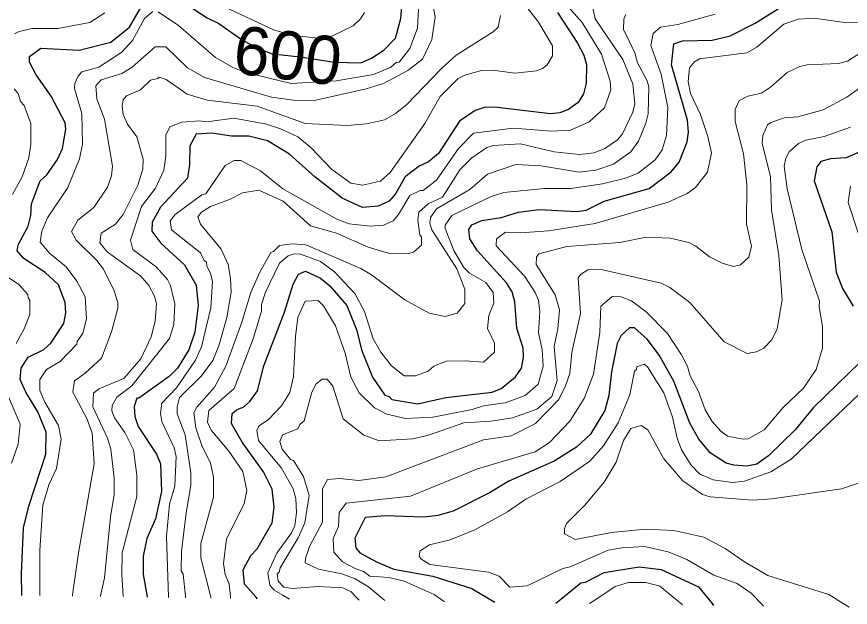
# Model space of a CAD drawing. Extents: x 673.3 to 698.5, y 6984.3 to 7012.3.
# Drawn here: x 678.213 to 679.596, y 6984.53 to 6985.511 of the extents above; entities that cross this region are included whole.
import ezdxf
from ezdxf.enums import TextEntityAlignment as Align

# ---------------------------------------------------------------- set-up
doc = ezdxf.new("R2010")
doc.units = 0
doc.header["$LTSCALE"] = 0.032
doc.layers.add('1', color=7, linetype='Continuous', lineweight=25)
doc.layers.add('2', color=7, linetype='Continuous', lineweight=13)
doc.layers.add('61', color=7, linetype='Continuous')

msp = doc.modelspace()

# ---------------------------------------------------------------- linework, layer by layer
at = {"layer": '1'}
for points in [[(678.2216, 6984.5503), (678.2208, 6984.5864), (678.2243, 6984.6624), (678.2328, 6984.6983), (678.2611, 6984.7846), (678.2617, 6984.8213), (678.2481, 6984.8546), (678.2282, 6984.8877), (678.2189, 6984.9087), (678.2201, 6984.9273), (678.2317, 6984.9453), (678.258, 6984.9585), (678.2697, 6984.9686), (678.2911, 6985.0015), (678.2943, 6985.0191), (678.2934, 6985.0361), (678.2821, 6985.0658), (678.2604, 6985.0859), (678.2248, 6985.1091), (678.2138, 6985.1221), (678.2152, 6985.1319), (678.2317, 6985.1631), (678.2365, 6985.1806), (678.2376, 6985.1998), (678.2518, 6985.2382), (678.2631, 6985.2482), (678.2807, 6985.2738), (678.2887, 6985.2917), (678.2943, 6985.3236), (678.2935, 6985.3345), (678.2703, 6985.3784), (678.2453, 6985.4138), (678.2342, 6985.4353), (678.2341, 6985.4442), (678.2531, 6985.4583), (678.3166, 6985.4552), (678.369, 6985.4685), (678.4003, 6985.493), (678.4288, 6985.5432)], [(678.494, 6985.5311), (678.5291, 6985.5084), (678.5483, 6985.4994), (678.5875, 6985.4717), (678.6144, 6985.4577), (678.6371, 6985.4491), (678.6835, 6985.4437), (678.7395, 6985.4348), (678.7837, 6985.434), (678.8014, 6985.4419), (678.822, 6985.4551), (678.8415, 6985.4747), (678.8504, 6985.5074), (678.8521, 6985.527)], [(678.6127, 6984.5446), (678.6097, 6984.548), (678.5908, 6984.5691), (678.5888, 6984.5925), (678.6012, 6984.6165), (678.6119, 6984.6275), (678.6367, 6984.6706), (678.6404, 6984.6966), (678.6371, 6984.7265), (678.6227, 6984.7553), (678.587, 6984.8046), (678.5691, 6984.8355), (678.5706, 6984.8518), (678.5777, 6984.8581), (678.5899, 6984.8631), (678.5996, 6984.8719), (678.6127, 6984.8899), (678.6229, 6984.9311), (678.6573, 6985.0204), (678.6716, 6985.0669), (678.6803, 6985.0835), (678.692, 6985.0884), (678.7169, 6985.0764), (678.7326, 6985.0639), (678.7609, 6985.0314), (678.7773, 6984.9897), (678.7851, 6984.9579), (678.8032, 6984.9122), (678.824, 6984.8825), (678.831, 6984.8801), (678.8352, 6984.8753), (678.8785, 6984.868), (678.9251, 6984.8787), (679.0017, 6984.8874), (679.0169, 6984.8935), (679.0404, 6984.913), (679.0508, 6984.9275), (679.0541, 6984.9458), (679.0533, 6984.9607), (679.0427, 6984.9936), (679.0395, 6985.0373), (679.0353, 6985.0539), (679.0258, 6985.0689), (678.9773, 6985.1222), (678.9646, 6985.1419), (678.963, 6985.1575), (678.968, 6985.1651), (678.9847, 6985.1723), (679.0167, 6985.1774), (679.0454, 6985.1862), (679.0799, 6985.1904), (679.1424, 6985.1872), (679.1581, 6985.1896), (679.1877, 6985.2042), (679.2623, 6985.2253), (679.299, 6985.2529), (679.3121, 6985.2691), (679.3254, 6985.3031), (679.3277, 6985.3188), (679.3262, 6985.3389), (679.2993, 6985.4304), (679.3033, 6985.4653), (679.3178, 6985.4705), (679.3671, 6985.4714), (679.3969, 6985.479), (679.4383, 6985.4997), (679.4904, 6985.5323)], [(679.1103, 6985.5174), (679.1436, 6985.4667), (679.1542, 6985.4464), (679.1584, 6985.4314), (679.1578, 6985.4002), (679.1535, 6985.3827), (679.1447, 6985.3682), (679.1288, 6985.3564), (679.1141, 6985.3508), (679.0988, 6985.3493), (679.0056, 6985.3606), (678.989, 6985.3598), (678.9737, 6985.3546), (678.9478, 6985.3373), (678.9126, 6985.2835), (678.8962, 6985.2695), (678.8809, 6985.2626), (678.8575, 6985.2446), (678.8415, 6985.2165), (678.831, 6985.2043), (678.8128, 6985.1961), (678.7868, 6985.1938), (678.7528, 6985.2091), (678.7078, 6985.2445), (678.6654, 6985.2826), (678.6293, 6985.3043), (678.5981, 6985.3125), (678.5691, 6985.3125), (678.5369, 6985.3174), (678.5109, 6985.3157), (678.5003, 6985.296), (678.4995, 6985.265), (678.4961, 6985.2425), (678.4516, 6985.1944), (678.4377, 6985.1697), (678.4369, 6985.1548), (678.4518, 6985.1347), (678.4913, 6985.0985), (678.5109, 6985.065)], [(679.6245, 6985.2916), (679.5896, 6985.2763), (679.5635, 6985.2745), (679.5474, 6985.27), (679.5404, 6985.2612), (679.5363, 6985.2379), (679.5654, 6985.1536), (679.5725, 6985.0866), (679.583, 6985.0595), (679.6009, 6985.0302)], [(678.5109, 6985.065), (678.5142, 6985.0311), (678.5086, 6984.9871), (678.4988, 6984.9578), (678.4798, 6984.9271), (678.4659, 6984.9134), (678.4154, 6984.8773), (678.4125, 6984.8774), (678.4077, 6984.8639), (678.4091, 6984.8471), (678.4142, 6984.8302), (678.4451, 6984.7846), (678.4515, 6984.7685), (678.4531, 6984.7226), (678.4433, 6984.6774), (678.4287, 6984.6448), (678.423, 6984.6151), (678.423, 6984.5848), (678.4288, 6984.5512), (678.4295, 6984.5473)], [(679.6127, 6984.9372), (679.5352, 6984.862), (679.5049, 6984.825), (679.4607, 6984.7818), (679.4409, 6984.7678), (679.4245, 6984.7646), (679.4027, 6984.7662), (679.3904, 6984.7699), (679.3639, 6984.7869), (679.3449, 6984.8092), (679.33, 6984.8359), (679.3032, 6984.9057), (679.2791, 6984.9488), (679.2595, 6984.9751), (679.2379, 6984.9941), (679.2296, 6984.9941), (679.2161, 6984.9817), (679.2092, 6984.9682), (679.1999, 6984.9213), (679.1957, 6984.8819), (679.1886, 6984.8568), (679.1651, 6984.8177), (679.1419, 6984.7961), (679.1048, 6984.7731)], [(679.1048, 6984.7731), (679.0295, 6984.7399), (678.9977, 6984.7204), (678.9374, 6984.69), (678.9118, 6984.6829), (678.8883, 6984.6798), (678.8241, 6984.6823), (678.7911, 6984.6797), (678.7741, 6984.6452), (678.7756, 6984.6289), (678.7823, 6984.6208), (678.8108, 6984.6051), (678.8387, 6984.5939), (678.9034, 6984.5819), (678.9681, 6984.5616), (678.9996, 6984.543), (679.0065, 6984.5389)], [(679.1077, 6984.5375), (679.1158, 6984.544), (679.1493, 6984.571), (679.157, 6984.5724), (679.188, 6984.5881), (679.2461, 6984.5975), (679.2825, 6984.5933), (679.3441, 6984.5645), (679.3669, 6984.5365), (679.3692, 6984.5337)]]:
    msp.add_lwpolyline(points, dxfattribs=at)
at = {"layer": '2'}
for points in [[(678.3054, 6984.5491), (678.3057, 6984.5512), (678.3155, 6984.6209), (678.3416, 6984.7686), (678.3381, 6984.8196), (678.3292, 6984.8438), (678.3058, 6984.8875), (678.309, 6984.9062), (678.3266, 6984.9187), (678.3537, 6984.944), (678.3703, 6984.9877), (678.3806, 6985.0268), (678.3806, 6985.0362), (678.3745, 6985.0558), (678.3569, 6985.0913), (678.346, 6985.1061), (678.3116, 6985.1397), (678.3041, 6985.1539), (678.3141, 6985.1726), (678.3411, 6985.194), (678.3634, 6985.2276), (678.3701, 6985.2464), (678.3716, 6985.2627), (678.3586, 6985.3402), (678.3461, 6985.3742), (678.3442, 6985.3959), (678.3533, 6985.4058), (678.3875, 6985.4165), (678.4043, 6985.4265), (678.4429, 6985.4606), (678.4603, 6985.4606), (678.4965, 6985.4256), (678.5243, 6985.4097), (678.6356, 6985.3768), (678.6766, 6985.3715), (678.7094, 6985.372), (678.7929, 6985.3909), (678.8217, 6985.3999), (678.8622, 6985.421), (678.8862, 6985.4403), (678.9019, 6985.4725), (678.9075, 6985.5096), (678.8824, 6985.651)], [(678.3899, 6984.5478), (678.3898, 6984.5487), (678.3871, 6984.5848), (678.388, 6984.621), (678.4123, 6984.7142), (678.4124, 6984.7496), (678.4065, 6984.7919), (678.3922, 6984.8207), (678.3751, 6984.8449), (678.3709, 6984.8565), (678.3715, 6984.8653), (678.3793, 6984.8794), (678.4039, 6984.8977), (678.4665, 6984.9765), (678.4734, 6984.9996), (678.4751, 6985.034), (678.4679, 6985.0644), (678.463, 6985.0745), (678.4451, 6985.095), (678.4055, 6985.124), (678.4018, 6985.1396), (678.4198, 6985.1955), (678.4433, 6985.2262), (678.4568, 6985.2561), (678.4604, 6985.2798), (678.4604, 6985.3139), (678.4672, 6985.328), (678.4872, 6985.3353), (678.5164, 6985.3377), (678.5286, 6985.3362), (678.573, 6985.3419), (678.6272, 6985.3321), (678.6508, 6985.3245), (678.6793, 6985.3111), (678.7018, 6985.2928), (678.7354, 6985.2576), (678.7673, 6985.2345), (678.787, 6985.2312), (678.8165, 6985.2378), (678.8325, 6985.2521), (678.8903, 6985.3335), (678.9158, 6985.3779), (678.9453, 6985.4082), (678.9563, 6985.4137), (678.9841, 6985.421), (679.0023, 6985.4216), (679.0401, 6985.4168), (679.0756, 6985.4209), (679.0853, 6985.4243), (679.093, 6985.4305), (679.102, 6985.4453), (679.1021, 6985.4621), (679.0787, 6985.5013), (679.0304, 6985.564)], [(678.8799, 6985.5232), (678.8782, 6985.4915), (678.8651, 6985.4576), (678.8473, 6985.435), (678.8427, 6985.4347), (678.8336, 6985.427), (678.805, 6985.4144), (678.7431, 6985.4039), (678.6684, 6985.3996), (678.591, 6985.4186), (678.5715, 6985.4264), (678.5426, 6985.443), (678.4814, 6985.4959), (678.4477, 6985.5184)], [(679.1292, 6985.5257), (679.1514, 6985.501), (679.1833, 6985.4483), (679.1975, 6985.4036), (679.199, 6985.3891), (679.1885, 6985.359), (679.1628, 6985.3358), (679.1317, 6985.3224), (679.1003, 6985.3207), (679.0367, 6985.3255), (678.9712, 6985.3174), (678.9462, 6985.2916), (678.9097, 6985.239), (678.8874, 6985.2219), (678.8826, 6985.2219), (678.8651, 6985.2139), (678.8464, 6985.1822), (678.8376, 6985.1719), (678.8217, 6985.1643), (678.7992, 6985.1628), (678.7646, 6985.1668), (678.7441, 6985.1744), (678.6544, 6985.2248), (678.6174, 6985.2549), (678.5846, 6985.2718), (678.574, 6985.2718), (678.5589, 6985.2637), (678.5267, 6985.2168), (678.5202, 6985.2149), (678.476, 6985.1822), (678.4678, 6985.1716), (678.4697, 6985.1569), (678.518, 6985.1189), (678.5242, 6985.1057), (678.528, 6985.1029), (678.5282, 6985.0967), (678.5343, 6985.0851), (678.5379, 6985.0709), (678.5353, 6985.0273), (678.5195, 6984.9629)], [(678.4932, 6984.5463), (678.4929, 6984.5491), (678.4889, 6984.5853), (678.4857, 6984.5911), (678.4865, 6984.6233), (678.4939, 6984.6874), (678.5019, 6984.7325), (678.5019, 6984.7536), (678.4923, 6984.8168), (678.4792, 6984.8517), (678.4792, 6984.8633), (678.4833, 6984.8784), (678.5195, 6984.9146), (678.5381, 6984.9402), (678.5481, 6984.9645), (678.5615, 6985.0115), (678.5687, 6985.0534), (678.5679, 6985.0767), (678.5638, 6985.0992), (678.5523, 6985.1246), (678.5181, 6985.1663), (678.5134, 6985.1786), (678.5196, 6985.1859), (678.5343, 6985.1955), (678.5661, 6985.2069), (678.5877, 6985.2185), (678.6149, 6985.2229), (678.6549, 6985.2044), (678.7003, 6985.1635), (678.7436, 6985.1511), (678.7962, 6985.1279), (678.8299, 6985.1182), (678.8601, 6985.1171), (678.8714, 6985.1195), (678.8847, 6985.1316), (678.8847, 6985.1453), (678.8821, 6985.1477), (678.8783, 6985.1735), (678.8803, 6985.186), (678.8959, 6985.1999), (678.9197, 6985.2109), (678.9482, 6985.2564), (678.9681, 6985.2763), (678.9933, 6985.2935), (679.004, 6985.297), (679.0487, 6985.2995), (679.1049, 6985.2864), (679.1468, 6985.2817), (679.1714, 6985.2845), (679.1888, 6985.2918), (679.21, 6985.3064), (679.2181, 6985.3161), (679.2353, 6985.3522), (679.2389, 6985.3659), (679.2356, 6985.3992), (679.2186, 6985.4396), (679.173, 6985.5067), (679.169, 6985.5253)], [(678.5567, 6985.5277), (678.6393, 6985.4888), (678.6714, 6985.4793), (678.7188, 6985.4744), (678.7359, 6985.4781), (678.7715, 6985.4955), (678.7835, 6985.5067), (678.7901, 6985.5175)], [(678.209, 6985.482), (678.2168, 6985.486), (678.2385, 6985.4908), (678.2811, 6985.4909), (678.3341, 6985.501), (678.359, 6985.5169)], [(678.4386, 6985.5193), (678.4251, 6985.5075), (678.4053, 6985.4708), (678.3876, 6985.4515), (678.3492, 6985.4267), (678.3211, 6985.419), (678.3148, 6985.4119), (678.3092, 6985.3996), (678.309, 6985.3911), (678.3211, 6985.35), (678.322, 6985.2992), (678.3171, 6985.2749), (678.298, 6985.2272), (678.2639, 6985.1768), (678.2544, 6985.1544), (678.252, 6985.1361), (678.268, 6985.1174), (678.2948, 6985.0954), (678.3129, 6985.0718), (678.3267, 6985.0455), (678.3286, 6985.0092), (678.3229, 6984.9855), (678.3133, 6984.9714), (678.3129, 6984.9673), (678.2848, 6984.9382), (678.2626, 6984.9249), (678.2512, 6984.9083), (678.2512, 6984.8902), (678.2594, 6984.8709), (678.282, 6984.8324), (678.2869, 6984.8093), (678.2789, 6984.7607), (678.2664, 6984.7337), (678.256, 6984.6998), (678.2511, 6984.6252), (678.2512, 6984.5498)], [(679.0157, 6985.5123), (679.0121, 6985.4932), (679.0037, 6985.4853), (678.9422, 6985.4465), (678.9179, 6985.4247), (678.8598, 6985.3642), (678.8414, 6985.3499), (678.8231, 6985.3396), (678.7933, 6985.3329), (678.762, 6985.3297), (678.6914, 6985.3334), (678.6117, 6985.3621), (678.5291, 6985.372), (678.4959, 6985.3817), (678.4607, 6985.4061), (678.4492, 6985.4103), (678.4469, 6985.4077), (678.4351, 6985.4052), (678.4181, 6985.3889), (678.3953, 6985.3791), (678.3897, 6985.3727), (678.3879, 6985.3627), (678.3897, 6985.3482), (678.397, 6985.3322), (678.4124, 6985.3109), (678.4228, 6985.2741), (678.4222, 6985.2575), (678.4139, 6985.231), (678.3895, 6985.182), (678.3768, 6985.1664), (678.3531, 6985.1514), (678.3506, 6985.1354), (678.3631, 6985.1202), (678.4191, 6985.0802), (678.4322, 6985.0644), (678.4416, 6985.0465), (678.4449, 6985.0338), (678.4426, 6985.0053), (678.4358, 6984.9794), (678.4187, 6984.9426), (678.3905, 6984.9103), (678.3492, 6984.8932), (678.3404, 6984.8859), (678.3392, 6984.8633), (678.3635, 6984.8109), (678.3693, 6984.7927), (678.3749, 6984.7447), (678.3749, 6984.7178), (678.3684, 6984.6806), (678.3586, 6984.5796), (678.3522, 6984.5496), (678.3519, 6984.5484)], [(678.5679, 6984.5453), (678.5675, 6984.5488), (678.5654, 6984.569), (678.5589, 6984.5846), (678.5559, 6984.603), (678.5608, 6984.644), (678.5901, 6984.7024), (678.5948, 6984.7244), (678.5884, 6984.756), (678.5647, 6984.7897), (678.5358, 6984.8245), (678.5297, 6984.8378), (678.5317, 6984.8569), (678.5736, 6984.8934), (678.6051, 6984.9759), (678.6191, 6985.022), (678.6194, 6985.033), (678.6257, 6985.0534), (678.6489, 6985.1017), (678.6635, 6985.1138), (678.6733, 6985.117), (678.6839, 6985.1163), (678.717, 6985.1041), (678.7403, 6985.0871), (678.7742, 6985.0514), (678.7901, 6985.0213), (678.8047, 6984.976), (678.8173, 6984.954), (678.8347, 6984.931), (678.8557, 6984.9148), (678.8747, 6984.9143), (678.8956, 6984.9222), (678.9052, 6984.9306), (678.9255, 6984.9387), (678.9571, 6984.9396), (678.9877, 6984.9372), (679.006, 6984.9537), (679.006, 6984.9689), (678.9939, 6984.9929), (678.9963, 6985.0145), (679.0044, 6985.0352), (679.0037, 6985.053), (678.9916, 6985.0697), (678.9642, 6985.0851), (678.955, 6985.0942), (678.9382, 6985.1223), (678.9238, 6985.1589), (678.9241, 6985.1646), (678.9352, 6985.1804), (679.0004, 6985.2123), (679.021, 6985.2187), (679.0883, 6985.2254), (679.1324, 6985.2256), (679.1851, 6985.2333), (679.2229, 6985.2423), (679.2443, 6985.2511), (679.2722, 6985.2732), (679.284, 6985.2895), (679.291, 6985.3136), (679.2935, 6985.3601), (679.2822, 6985.4149), (679.2651, 6985.4625), (679.2691, 6985.4825), (679.2815, 6985.4931), (679.3098, 6985.4974), (679.3718, 6985.5147)], [(679.2235, 6985.5142), (679.2202, 6985.5066), (679.2196, 6985.4892), (679.2384, 6985.4505), (679.2431, 6985.4341), (679.2592, 6985.4041), (679.2618, 6985.394), (679.2608, 6985.3495), (679.257, 6985.334), (679.2445, 6985.3042), (679.2318, 6985.286), (679.2034, 6985.2659), (679.1737, 6985.2561), (679.1461, 6985.2523), (679.0832, 6985.2629), (679.0414, 6985.2653), (678.9939, 6985.249), (678.9651, 6985.2236), (678.9094, 6985.1914), (678.8995, 6985.1775), (678.8987, 6985.1679), (678.9017, 6985.1566), (678.9431, 6985.0922), (678.9564, 6985.0585), (678.9564, 6985.0344), (678.944, 6985.0187), (678.9241, 6985.0129), (678.8975, 6985.0183), (678.8568, 6985.0407), (678.8014, 6985.0822)], [(679.6103, 6985.5013), (679.5904, 6985.5002), (679.5365, 6985.508), (679.5097, 6985.5062), (679.4858, 6985.4982), (679.4411, 6985.4601), (679.4245, 6985.4504), (679.3461, 6985.4405), (679.3375, 6985.4355), (679.3296, 6985.4256)], [(678.781, 6984.5422), (678.7784, 6984.545), (678.7676, 6984.5565), (678.7543, 6984.5625), (678.7131, 6984.565), (678.6708, 6984.5617), (678.6564, 6984.564), (678.6466, 6984.5737), (678.6454, 6984.5858), (678.6485, 6984.5888), (678.6499, 6984.5961), (678.68, 6984.6458), (678.6909, 6984.6704), (678.6983, 6984.7157), (678.689, 6984.7477), (678.6725, 6984.7738), (678.6674, 6984.7759), (678.6535, 6984.793), (678.6494, 6984.8058), (678.6542, 6984.8164), (678.6795, 6984.8265), (678.6828, 6984.8336), (678.6902, 6984.8396), (678.7026, 6984.8874), (678.7101, 6984.901), (678.72, 6984.9092), (678.7282, 6984.9089), (678.7373, 6984.8972), (678.7549, 6984.8431), (678.7892, 6984.8159), (678.815, 6984.8068), (678.8704, 6984.8101), (678.8945, 6984.8154), (678.9547, 6984.8366), (679.0001, 6984.8393), (679.0356, 6984.8449), (679.076, 6984.8593), (679.1011, 6984.88), (679.1095, 6984.907), (679.1047, 6984.9634), (679.111, 6984.9927), (679.1135, 6985.0242), (679.1062, 6985.0487), (679.0751, 6985.0991), (679.0753, 6985.1116), (679.0793, 6985.1169), (679.1259, 6985.1293), (679.2138, 6985.136), (679.2577, 6985.1448), (679.2974, 6985.143), (679.3281, 6985.1357), (679.3398, 6985.1297), (679.3626, 6985.1119), (679.3837, 6985.1014), (679.4024, 6985.096), (679.4139, 6985.0987), (679.4279, 6985.1117), (679.4321, 6985.1298), (679.4238, 6985.1663), (679.4246, 6985.2317), (679.4189, 6985.2832), (679.4052, 6985.3368), (679.4052, 6985.3565), (679.4118, 6985.3712), (679.4259, 6985.3789), (679.4486, 6985.3835), (679.4639, 6985.3933), (679.4917, 6985.4178), (679.5123, 6985.4279), (679.5244, 6985.4306), (679.5767, 6985.433), (679.5918, 6985.4368), (679.6225, 6985.4569)], [(679.6876, 6985.4463), (679.5906, 6985.3772), (679.5512, 6985.3559), (679.5089, 6985.3444), (679.4868, 6985.3425), (679.4644, 6985.3352), (679.4588, 6985.331), (679.451, 6985.3132), (679.45, 6985.3005), (679.4637, 6985.2447), (679.4654, 6985.1898), (679.4776, 6985.1141), (679.4834, 6985.0406), (679.4749, 6984.9928), (679.466, 6984.9745), (679.4529, 6984.9606), (679.4403, 6984.9543), (679.425, 6984.9518), (679.387, 6984.971), (679.33, 6985.036), (679.2966, 6985.0613), (679.2825, 6985.0681), (679.1828, 6985.091), (679.1604, 6985.0902), (679.1486, 6985.0826), (679.1446, 6985.0769), (679.1486, 6985.0178), (679.134, 6984.9532), (679.1307, 6984.9184), (679.1238, 6984.8977), (679.1123, 6984.8755), (679.0739, 6984.8355), (679.0336, 6984.8152), (678.9873, 6984.8084), (678.8254, 6984.7472), (678.7808, 6984.7409), (678.7485, 6984.7441), (678.7285, 6984.7423), (678.7201, 6984.7268), (678.7202, 6984.6719), (678.6988, 6984.6312), (678.692, 6984.6116), (678.6918, 6984.6043), (678.7136, 6984.5935), (678.7526, 6984.5862), (678.7743, 6984.5778), (678.7966, 6984.5643), (678.8172, 6984.5471), (678.8238, 6984.5416)], [(679.3296, 6985.4256), (679.327, 6985.403), (679.3311, 6985.3828), (679.3474, 6985.3482), (679.3599, 6985.3115), (679.366, 6985.2847), (679.3595, 6985.2523), (679.3395, 6985.2268), (679.3256, 6985.2169), (679.2942, 6985.2028), (679.173, 6985.1672), (679.0955, 6985.1552), (679.0489, 6985.1521), (679.0243, 6985.153), (679.009, 6985.1418), (679.0086, 6985.1304), (679.0559, 6985.0794), (679.0735, 6985.053), (679.0786, 6985.0403), (679.081, 6985.0213), (679.0786, 6984.9859), (679.0851, 6984.9585), (679.0868, 6984.9304), (679.0783, 6984.9005), (679.0564, 6984.8821), (679.0235, 6984.8696), (678.9876, 6984.8647), (678.9685, 6984.8587), (678.9033, 6984.846), (678.8581, 6984.8435), (678.827, 6984.8512), (678.8065, 6984.8615), (678.781, 6984.8865), (678.7674, 6984.9122), (678.7578, 6984.9523), (678.7418, 6984.9973), (678.722, 6985.0306), (678.7134, 6985.0397), (678.6916, 6985.0387), (678.6796, 6985.0112), (678.6755, 6984.9796), (678.6721, 6984.9133), (678.6664, 6984.8868), (678.6525, 6984.8645), (678.6308, 6984.842), (678.6155, 6984.8314), (678.6112, 6984.8244), (678.6141, 6984.8073), (678.6522, 6984.7615), (678.6716, 6984.7273), (678.6763, 6984.7112), (678.6771, 6984.6878), (678.6745, 6984.6657), (678.6691, 6984.654), (678.6444, 6984.6201), (678.6299, 6984.5877), (678.633, 6984.567), (678.6401, 6984.5588), (678.6544, 6984.5504), (678.6655, 6984.5439)], [(678.2058, 6985.2154), (678.222, 6985.2445), (678.2331, 6985.2761), (678.2364, 6985.2993), (678.2365, 6985.3334), (678.2253, 6985.3633), (678.219, 6985.3696), (678.2156, 6985.3828), (678.2087, 6985.391)], [(678.9227, 6984.5401), (678.9225, 6984.5403), (678.9057, 6984.5517), (678.856, 6984.5737), (678.8308, 6984.5797), (678.7989, 6984.5819), (678.7884, 6984.5901), (678.7758, 6984.5941), (678.7537, 6984.606), (678.739, 6984.6221), (678.7382, 6984.6444), (678.7471, 6984.6644), (678.748, 6984.6877), (678.7599, 6984.7031), (678.8662, 6984.7146), (678.9776, 6984.7604), (679.0731, 6984.7887), (679.0973, 6984.8041), (679.1309, 6984.8394), (679.1547, 6984.8769), (679.1698, 6984.9174), (679.1803, 6984.9866), (679.1825, 6985.0303), (679.2013, 6985.0463), (679.2161, 6985.0456), (679.2333, 6985.0389), (679.2574, 6985.0206), (679.2929, 6984.985), (679.3162, 6984.9496), (679.326, 6984.9301), (679.3306, 6984.9144), (679.3443, 6984.8886), (679.3554, 6984.8584), (679.3672, 6984.8386), (679.3814, 6984.8225), (679.3925, 6984.8143), (679.4186, 6984.8092), (679.4268, 6984.81), (679.453, 6984.8247), (679.485, 6984.8622), (679.5185, 6984.8942), (679.5395, 6984.9249), (679.55, 6984.9607), (679.55, 6984.9969), (679.5445, 6985.0289), (679.545, 6985.0384), (679.5157, 6985.1242), (679.4914, 6985.2249), (679.4866, 6985.2624), (679.4891, 6985.2759), (679.4946, 6985.2862), (679.51, 6985.3001), (679.5222, 6985.3054), (679.5528, 6985.3118), (679.5963, 6985.3271)], [(679.5965, 6985.2291), (679.5926, 6985.2021), (679.6093, 6985.1519)], [(678.8014, 6985.0822), (678.7841, 6985.0925), (678.6925, 6985.1317), (678.6702, 6985.1334), (678.6489, 6985.131), (678.6391, 6985.1207), (678.6345, 6985.1194), (678.6157, 6985.0856), (678.6017, 6985.0529), (678.5867, 6985.0034), (678.5601, 6984.9304), (678.5411, 6984.8957), (678.5116, 6984.8628), (678.5069, 6984.8532), (678.51, 6984.8284), (678.5202, 6984.799), (678.5344, 6984.7696), (678.5394, 6984.7471), (678.5394, 6984.7132), (678.5182, 6984.6362), (678.5183, 6984.6123), (678.5347, 6984.5496), (678.5357, 6984.5457)], [(678.2122, 6984.9683), (678.2254, 6984.9923), (678.2348, 6985.0162), (678.2349, 6985.0401), (678.2317, 6985.0441), (678.2314, 6985.0497), (678.2159, 6985.0668), (678.1608, 6985.1025)], [(678.5195, 6984.9629), (678.5098, 6984.9406), (678.4781, 6984.8946), (678.4538, 6984.8694), (678.4515, 6984.8519), (678.4535, 6984.8386), (678.4741, 6984.7949), (678.4776, 6984.7809), (678.4751, 6984.7312), (678.4662, 6984.7018), (678.4614, 6984.6485), (678.4646, 6984.5479), (678.4646, 6984.5468)], [(679.4981, 6984.7765), (679.4646, 6984.7555), (679.4204, 6984.74), (679.4009, 6984.7377), (679.3685, 6984.7417), (679.3463, 6984.7511), (679.3324, 6984.7664), (679.3161, 6984.7919), (679.309, 6984.8112), (679.3014, 6984.8462), (679.2869, 6984.8861), (679.2595, 6984.9295), (679.2543, 6984.9337), (679.2418, 6984.9294), (679.2414, 6984.9252), (679.2379, 6984.9222), (679.2302, 6984.8831), (679.211, 6984.8363), (679.1869, 6984.7984), (679.1639, 6984.7732), (679.1145, 6984.7394), (679.0577, 6984.7101), (679.0275, 6984.6889), (678.973, 6984.6588), (678.9323, 6984.6424), (678.8981, 6984.6342), (678.8822, 6984.6241), (678.8808, 6984.6155), (678.8838, 6984.6108), (678.8983, 6984.6014), (678.9958, 6984.5885), (679.0134, 6984.582), (679.031, 6984.5637), (679.0601, 6984.5659), (679.1193, 6984.595), (679.1313, 6984.5978), (679.1942, 6984.6252), (679.2173, 6984.6293), (679.2545, 6984.6312), (679.2942, 6984.6225), (679.3248, 6984.6096), (679.3695, 6984.5839), (679.4087, 6984.5701), (679.4318, 6984.5537), (679.4492, 6984.5357), (679.4523, 6984.5325)], [(678.2041, 6984.7695), (678.2153, 6984.8009), (678.2185, 6984.8342), (678.1877, 6984.9068)], [(679.6116, 6984.8847), (679.4981, 6984.7765)], [(679.5946, 6984.5304), (679.5842, 6984.537), (679.5607, 6984.5519), (679.4595, 6984.5834), (679.4204, 6984.6058), (679.3886, 6984.6278), (679.3533, 6984.6471), (679.3031, 6984.6578), (679.2566, 6984.6602), (679.2001, 6984.6544), (679.1396, 6984.6432), (679.1218, 6984.6525), (679.1218, 6984.6609), (679.1255, 6984.6694), (679.1549, 6984.6991), (679.1878, 6984.7379), (679.2077, 6984.7712), (679.22, 6984.807), (679.2319, 6984.8272), (679.2493, 6984.832), (679.2601, 6984.8247), (679.2866, 6984.7766), (679.3184, 6984.7405), (679.351, 6984.7179), (679.3639, 6984.7139), (679.4331, 6984.7083), (679.4659, 6984.7107), (679.5818, 6984.727), (679.618, 6984.7394)], [(679.1635, 6984.5367), (679.1724, 6984.5425), (679.2062, 6984.5648), (679.2284, 6984.5714), (679.2567, 6984.5714), (679.2799, 6984.5657), (679.3173, 6984.5349), (679.3179, 6984.5344)]]:
    msp.add_lwpolyline(points, dxfattribs=at)

# ---------------------------------------------------------------- texts
at = {"layer": '61'}
msp.add_text('600', height=0.08, rotation=353.076, dxfattribs=at).set_placement((678.658, 6985.4065), align=Align.CENTER)

doc.saveas('drawing.dxf')
